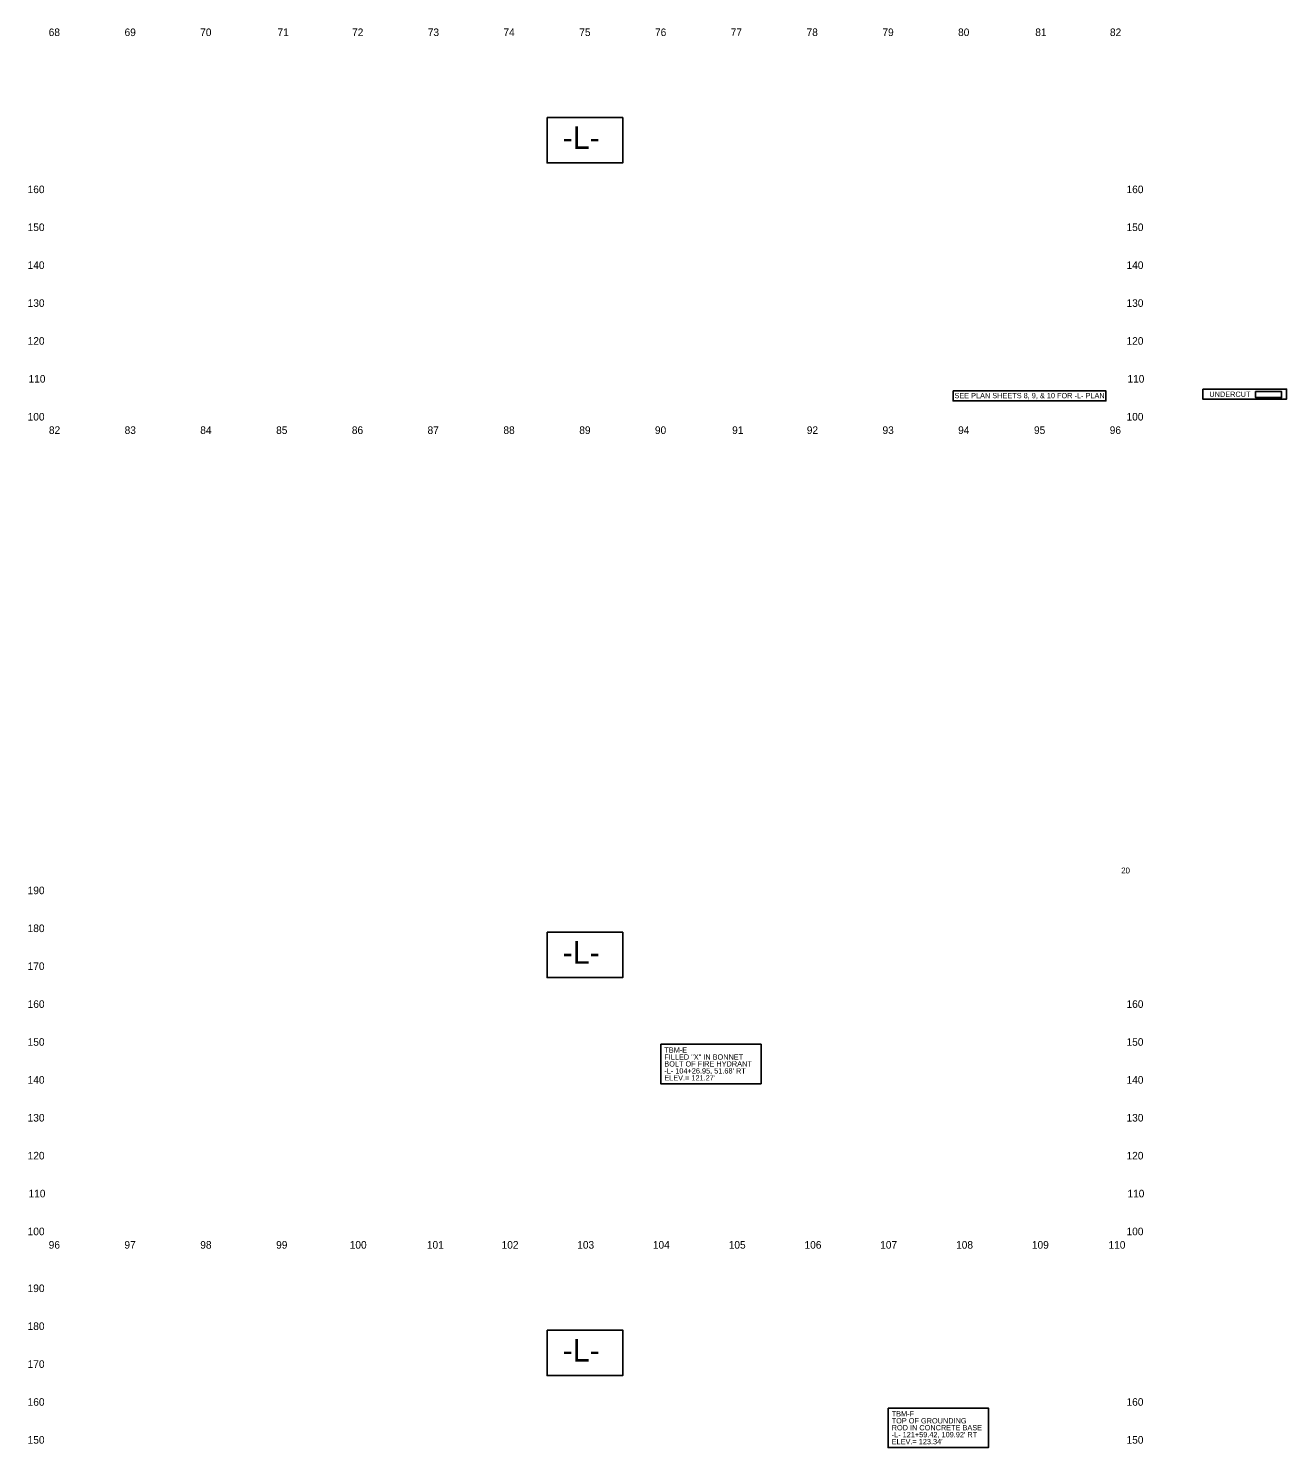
# Model space of a CAD drawing. Extents: x 2364289 to 2366249, y 588759 to 610062.
# Drawn here: x 2364469 to 2366129, y 604496 to 606369 of the extents above; entities that cross this region are included whole.
import ezdxf

# ---------------------------------------------------------------- set-up
doc = ezdxf.new("R2010")
doc.units = 0
for name, color, linetype in [('Exist Vertical Profile Horizontal Axis Label Major', 7, 'Continuous'), ('Exist Vertical Profile Vertical Axis Label', 7, 'Continuous'), ('Prop CMT Shallow Undercut', 7, 'Continuous'), ('Prop DSN Text', 7, 'Continuous'), ('Prop Grid Mask', 7, 'Continuous'), ('Sheet Data Field CELL', 7, 'Continuous')]:
    doc.layers.add(name, color=color, linetype=linetype)

msp = doc.modelspace()

# ---------------------------------------------------------------- linework, layer by layer
at = {"layer": 'Prop CMT Shallow Undercut'}
msp.add_lwpolyline([(2366088.3, 605890), (2366122.5, 605890), (2366122.5, 605882), (2366088.3, 605882)], close=True, dxfattribs=at)
msp.add_lwpolyline([(2366088.3, 605890), (2366122.5, 605890), (2366122.5, 605882), (2366088.3, 605882)], close=True, dxfattribs=at)
msp.add_lwpolyline([(2366088.3, 605882), (2366122.5, 605882), (2366122.5, 605890), (2366088.3, 605890), (2366088.3, 605882)], dxfattribs=at)
msp.add_lwpolyline([(2366088.3, 605882), (2366122.5, 605882), (2366122.5, 605890), (2366088.3, 605890), (2366088.3, 605882)], dxfattribs=at)
at = {"layer": 'Prop Grid Mask'}
for points in [[(2365153.5, 606251.5), (2365253.2, 606251.5), (2365253.2, 606191.6), (2365153.5, 606191.6)], [(2365689.1, 605890.7), (2365890.8, 605890.7), (2365890.8, 605877.5), (2365689.1, 605877.5)], [(2366018.5, 605893.1), (2366129.2, 605893.1), (2366129.2, 605879.9), (2366018.5, 605879.9)], [(2365153.5, 605176.5), (2365253.2, 605176.5), (2365253.2, 605116.6), (2365153.5, 605116.6)], [(2365303.3, 605028.7), (2365435.7, 605028.7), (2365435.7, 604976.5), (2365303.3, 604976.5)], [(2365153.5, 604651.5), (2365253.2, 604651.5), (2365253.2, 604591.6), (2365153.5, 604591.6)], [(2365603.3, 604548.7), (2365735.7, 604548.7), (2365735.7, 604496.5), (2365603.3, 604496.5)]]:
    msp.add_lwpolyline(points, close=True, dxfattribs=at)

# ---------------------------------------------------------------- texts
at = {"layer": 'Exist Vertical Profile Horizontal Axis Label Major'}
for s, p in [('68', (2364495.8, 606359)), ('69', (2364595.9, 606359)), ('70', (2364695.7, 606359)), ('71', (2364797.6, 606359)), ('72', (2364896.1, 606359)), ('73', (2364996, 606359)), ('74', (2365095.8, 606359)), ('75', (2365195.9, 606359)), ('76', (2365295.8, 606359)), ('77', (2365395.7, 606359)), ('78', (2365495.8, 606359)), ('79', (2365595.9, 606359)), ('80', (2365695.7, 606359)), ('81', (2365797.6, 606359)), ('82', (2365896.1, 606359)), ('82', (2364496.1, 605834)), ('83', (2364596, 605834)), ('84', (2364695.8, 605834)), ('85', (2364795.9, 605834)), ('86', (2364895.8, 605834)), ('87', (2364995.7, 605834)), ('88', (2365095.8, 605834)), ('89', (2365195.9, 605834)), ('90', (2365295.7, 605834)), ('91', (2365397.6, 605834)), ('92', (2365496.1, 605834)), ('93', (2365596, 605834)), ('94', (2365695.8, 605834)), ('95', (2365795.9, 605834)), ('96', (2365895.8, 605834)), ('96', (2364495.8, 604759)), ('97', (2364595.7, 604759)), ('98', (2364695.8, 604759)), ('99', (2364795.9, 604759)), ('100', (2364893, 604759)), ('101', (2364994.8, 604759)), ('102', (2365093.4, 604759)), ('103', (2365193.2, 604759)), ('104', (2365293, 604759)), ('105', (2365393.1, 604759)), ('106', (2365493.1, 604759)), ('107', (2365592.9, 604759)), ('108', (2365693.1, 604759)), ('109', (2365793.1, 604759)), ('110', (2365894.2, 604759))]:
    msp.add_text(s, height=10, dxfattribs=at).set_placement(p)
at = {"layer": 'Exist Vertical Profile Vertical Axis Label'}
for s, p in [('160', (2364468, 606151.7)), ('160', (2365918, 606151.7)), ('150', (2364468, 606101.7)), ('150', (2365918, 606101.7)), ('140', (2364468, 606051.7)), ('140', (2365918, 606051.7)), ('130', (2364468, 606001.7)), ('130', (2365918, 606001.7)), ('120', (2364468, 605951.7)), ('120', (2365918, 605951.7)), ('110', (2364469.2, 605901.7)), ('110', (2365919.2, 605901.7)), ('100', (2364468, 605851.7)), ('100', (2365918, 605851.7)), ('190', (2364468, 605226.7)), ('180', (2364468, 605176.7)), ('170', (2364468, 605126.7)), ('160', (2364468, 605076.7)), ('160', (2365918, 605076.7)), ('150', (2364468, 605026.7)), ('150', (2365918, 605026.7)), ('140', (2364468, 604976.7)), ('140', (2365918, 604976.7)), ('130', (2364468, 604926.7)), ('130', (2365918, 604926.7)), ('120', (2364468, 604876.7)), ('120', (2365918, 604876.7)), ('110', (2364469.2, 604826.7)), ('110', (2365919.2, 604826.7)), ('100', (2364468, 604776.7)), ('100', (2365918, 604776.7)), ('190', (2364468, 604701.7)), ('180', (2364468, 604651.7)), ('170', (2364468, 604601.7)), ('160', (2364468, 604551.7)), ('160', (2365918, 604551.7)), ('150', (2364468, 604501.7)), ('150', (2365918, 604501.7))]:
    msp.add_text(s, height=10, dxfattribs=at).set_placement(p)
at = {"layer": 'Prop DSN Text'}
for s, p in [('SEE PLAN SHEETS 8, 9, & 10 FOR -L- PLAN', (2365690.9, 605881.1)), ('UNDERCUT', (2366027.3, 605882.9)), ('TBM-E', (2365308.1, 605017.6)), ('FILLED "X" IN BONNET ', (2365308.1, 605008.4)), ("-L- 104+26.95, 51.68' RT", (2365308.1, 604990.1)), ('BOLT OF FIRE HYDRANT', (2365308.1, 604999.3)), ("ELEV.= 121.27'", (2365308.1, 604980.9)), ('TBM-F', (2365608.1, 604537.6)), ('TOP OF GROUNDING ', (2365608.1, 604528.4)), ("-L- 121+59.42, 109.92' RT", (2365608.1, 604510.1)), ('ROD IN CONCRETE BASE', (2365608.1, 604519.3)), ("ELEV.= 123.34'", (2365608.1, 604500.9))]:
    msp.add_text(s, height=7, dxfattribs=at).set_placement(p)
at = {"layer": 'Prop Grid Mask'}
for p in [(2365174, 606210), (2365174, 605135), (2365174, 604610)]:
    msp.add_text('-L-', height=30, dxfattribs=at).set_placement(p)
at = {"layer": 'Sheet Data Field CELL'}
msp.add_text('20', height=7.75, dxfattribs=at).set_placement((2365911, 605254.1))

doc.saveas('drawing.dxf')
